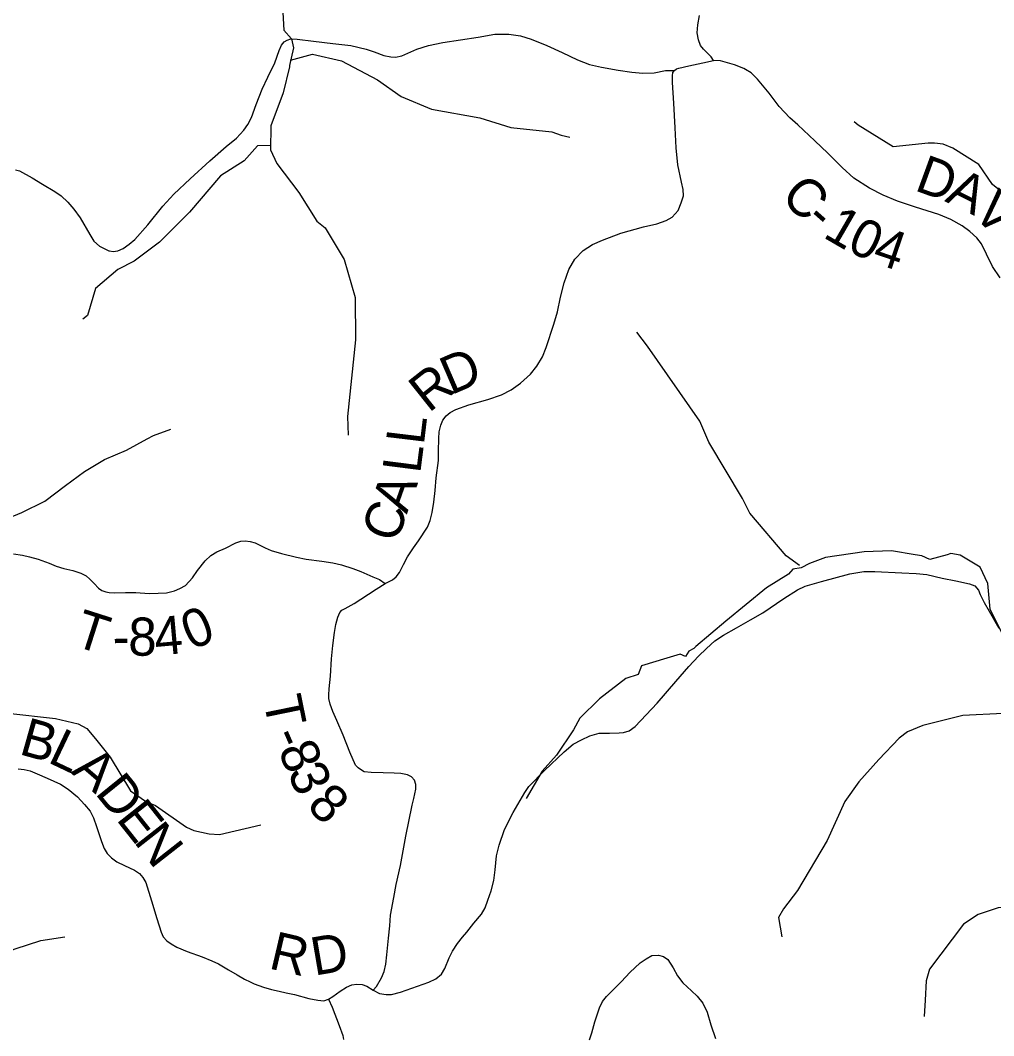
# Model space of a CAD drawing. Extents: x -1.8 to 75.7, y -2 to 25.
# Drawn here: x 6.256 to 7.704, y 15.471 to 16.983 of the extents above; entities that cross this region are included whole.
import ezdxf

# ---------------------------------------------------------------- set-up
doc = ezdxf.new("R2010")
doc.units = 0
for name, color, linetype in [('GM_X_County_Road', 7, 'Continuous'), ('GM_X_County_Road_Text', 7, 'Continuous'), ('GM_X_Minor_River', 7, 'Continuous'), ('GM_X_Township_Road', 7, 'Continuous'), ('GM_X_Township_Road_Text', 7, 'Continuous')]:
    doc.layers.add(name, color=color, linetype=linetype)

msp = doc.modelspace()

# ---------------------------------------------------------------- linework, layer by layer
at = {"layer": 'GM_X_County_Road'}
for points in [[(7.3351, 16.9097), (7.3325, 16.9113), (7.3187, 16.9167), (7.2978, 16.9227), (7.2872, 16.9231), (7.2841, 16.9283), (7.2785, 16.9339), (7.2724, 16.9398), (7.2679, 16.9452), (7.2648, 16.954), (7.2632, 16.9642), (7.2638, 16.9759), (7.2667, 16.9899)], [(7.7142, 16.5994), (7.7026, 16.6165), (7.6935, 16.6347), (7.6864, 16.6502), (7.6793, 16.659), (7.669, 16.6686), (7.6577, 16.6769), (7.6405, 16.6865), (7.6228, 16.6936), (7.5878, 16.7047), (7.5615, 16.7137), (7.5401, 16.7226), (7.5195, 16.7331), (7.4964, 16.7479), (7.479, 16.7638), (7.4574, 16.7849), (7.4383, 16.8036), (7.413, 16.8271), (7.401, 16.8377), (7.385, 16.8544), (7.3703, 16.8743), (7.3531, 16.8954), (7.3435, 16.9044), (7.3351, 16.9097)], [(6.2525, 15.8683), (6.2615, 15.8676), (6.2703, 15.8654), (6.2807, 15.8611), (6.2956, 15.8546), (6.3152, 15.8457), (6.3268, 15.8385), (6.3405, 15.8267), (6.3512, 15.8155), (6.3593, 15.8053), (6.3645, 15.7958), (6.369, 15.7829), (6.3763, 15.7606), (6.3805, 15.7499), (6.3848, 15.7423), (6.3912, 15.7359), (6.399, 15.7303), (6.4108, 15.7246), (6.4257, 15.7176), (6.433, 15.7129), (6.4381, 15.7068), (6.4422, 15.6991), (6.4506, 15.6722), (6.4587, 15.6456), (6.465, 15.6252), (6.4682, 15.6183), (6.4736, 15.6126), (6.4799, 15.6078), (6.4883, 15.6031), (6.5041, 15.5965), (6.5262, 15.5886), (6.5405, 15.5828), (6.5507, 15.5782), (6.5653, 15.5695), (6.5784, 15.5618), (6.5891, 15.5554), (6.5976, 15.5516), (6.6037, 15.5484), (6.6175, 15.5435), (6.6293, 15.5401), (6.641, 15.5376), (6.6514, 15.5351), (6.6638, 15.5328), (6.685, 15.5268), (6.6982, 15.524), (6.7074, 15.5234), (6.7142, 15.5256), (6.7207, 15.5297), (6.7318, 15.5376), (6.7413, 15.5433), (6.7492, 15.5469), (6.7567, 15.5482), (6.7644, 15.5473), (6.7714, 15.5448), (6.781, 15.5389), (6.7903, 15.534), (6.8002, 15.5324), (6.8082, 15.5326), (6.8217, 15.5363), (6.8466, 15.5451), (6.8635, 15.5509), (6.874, 15.5561), (6.8824, 15.563), (6.8875, 15.5712), (6.8939, 15.5871), (6.899, 15.5972), (6.9065, 15.6085), (6.9138, 15.6182), (6.9202, 15.6253), (6.9308, 15.6387), (6.9418, 15.6522), (6.9473, 15.6617), (6.9515, 15.6732), (6.9562, 15.6869), (6.9603, 15.7025), (6.9626, 15.7184), (6.9645, 15.7388), (6.9681, 15.7549), (6.9762, 15.7781), (6.9891, 15.8035), (7.0063, 15.8331), (7.0125, 15.8423), (7.0359, 15.866), (7.0652, 15.894), (7.0787, 15.9051), (7.0909, 15.9119), (7.1032, 15.9176), (7.1171, 15.9214), (7.1324, 15.9216), (7.147, 15.9221), (7.1534, 15.9225), (7.162, 15.9249), (7.1708, 15.9318), (7.2035, 15.9662), (7.2313, 15.9985), (7.2507, 16.0208), (7.2649, 16.0364), (7.277, 16.0479), (7.2894, 16.059), (7.3022, 16.0676), (7.3216, 16.0786), (7.3426, 16.0903), (7.3607, 16.1009), (7.3923, 16.1219), (7.4124, 16.1352), (7.4239, 16.1407), (7.4479, 16.1475), (7.4901, 16.1586), (7.5111, 16.1623), (7.5276, 16.1622), (7.5679, 16.1603), (7.589, 16.1595), (7.6047, 16.1576), (7.6275, 16.1524), (7.6479, 16.1483), (7.6683, 16.1441), (7.6766, 16.1409), (7.6818, 16.1343), (7.6844, 16.128), (7.6903, 16.1161), (7.6977, 16.1031), (7.7119, 16.0781)], [(7.1028, 15.4649), (7.1062, 15.4757), (7.1108, 15.4917), (7.1175, 15.513), (7.1223, 15.5223), (7.1281, 15.5297), (7.1502, 15.5518), (7.1628, 15.5656), (7.1782, 15.5795), (7.1871, 15.5858), (7.1957, 15.5906), (7.2053, 15.5914), (7.2128, 15.5893), (7.2196, 15.5849), (7.2274, 15.5721), (7.2336, 15.5604), (7.2419, 15.55), (7.2547, 15.5381), (7.2633, 15.5301), (7.2713, 15.5199), (7.2778, 15.5065), (7.2833, 15.4874), (7.2904, 15.4673)], [(6.7142, 15.5256), (6.7199, 15.5137), (6.7302, 15.4866), (6.7357, 15.4718), (6.7368, 15.4657)]]:
    msp.add_lwpolyline(points, dxfattribs=at)
at = {"layer": 'GM_X_Minor_River'}
for points in [[(6.5731, 17.2447), (6.5733, 17.2424), (6.5763, 17.2257), (6.5994, 17.1892), (6.618, 17.1471), (6.6437, 17.0992), (6.6521, 17.0749), (6.6536, 17.0449), (6.6521, 17.0198), (6.6465, 16.9943), (6.6476, 16.9681), (6.6594, 16.9552), (6.662, 16.9419), (6.656, 16.9157), (6.6564, 16.9134), (6.6466, 16.875), (6.6285, 16.8256), (6.6278, 16.7898), (6.6376, 16.7697), (6.6702, 16.7264), (6.6967, 16.6836), (6.7091, 16.6741), (6.7375, 16.6269)], [(6.6576, 16.9233), (6.6904, 16.9324), (6.7335, 16.9227), (6.7871, 16.8944), (6.8226, 16.8693), (6.8678, 16.8504), (6.9396, 16.8375), (6.9857, 16.8235), (7.0467, 16.8166), (7.0605, 16.8116), (7.0737, 16.8089)], [(7.7105, 16.7318), (7.7028, 16.7385), (7.6821, 16.7684), (7.6436, 16.7924), (7.629, 16.7986), (7.6162, 16.8001), (7.6071, 16.7997), (7.5548, 16.7945), (7.5028, 16.8265), (7.4966, 16.8317)], [(6.6279, 16.7964), (6.6085, 16.796), (6.5889, 16.7735), (6.5537, 16.7513), (6.5074, 16.6972), (6.4629, 16.6525), (6.4251, 16.6242), (6.4009, 16.612), (6.3676, 16.5837), (6.3557, 16.5434), (6.3486, 16.5377)], [(6.7375, 16.6269), (6.7542, 16.5701), (6.7545, 16.507), (6.7424, 16.3931), (6.7438, 16.3654)], [(7.4153, 16.1713), (7.3953, 16.1856), (7.3413, 16.2492), (7.3303, 16.2712), (7.2803, 16.3548), (7.2669, 16.386), (7.189, 16.4975), (7.173, 16.5185)], [(6.2049, 16.2283), (6.2578, 16.25), (6.2918, 16.2668), (6.3228, 16.2901), (6.3511, 16.3114), (6.381, 16.329), (6.4138, 16.3428), (6.4444, 16.3599), (6.4539, 16.3649), (6.4796, 16.3744)], [(7.7232, 16.0584), (7.7043, 16.096), (7.6993, 16.1063), (7.6955, 16.1443), (7.6845, 16.1689), (7.6543, 16.1867), (7.6407, 16.189), (7.6354, 16.1871), (7.6093, 16.1802), (7.5976, 16.1858), (7.5874, 16.187), (7.5522, 16.193), (7.5118, 16.1917), (7.4543, 16.1829), (7.4305, 16.1741), (7.418, 16.1676), (7.4056, 16.166), (7.3991, 16.1584), (7.3663, 16.1378), (7.3055, 16.0883), (7.2613, 16.0509), (7.2579, 16.0479), (7.2507, 16.0437), (7.2458, 16.036), (7.2375, 16.0391), (7.2178, 16.0333), (7.1804, 16.0218), (7.1751, 16.0089), (7.157, 16.0028), (7.1177, 15.9727), (7.0886, 15.9441), (7.0788, 15.9266), (7.0539, 15.8889), (7.0323, 15.8653), (7.0086, 15.8246)], [(6.0038, 16.0741), (6.0123, 16.0492), (6.0352, 16.0227), (6.0596, 16.0077), (6.1006, 15.9999), (6.1786, 15.9783), (6.2372, 15.9516), (6.3078, 15.9436), (6.3416, 15.9354), (6.3546, 15.9287), (6.3676, 15.9132), (6.3894, 15.8859), (6.4197, 15.836), (6.4433, 15.8194), (6.457, 15.8141), (6.5031, 15.7817), (6.5138, 15.7765), (6.5369, 15.772), (6.5521, 15.7706), (6.6135, 15.7853)], [(7.7295, 15.9561), (7.7186, 15.9508), (7.6583, 15.9478), (7.5988, 15.933), (7.5763, 15.9236), (7.5638, 15.9142), (7.5337, 15.8824), (7.5035, 15.8492), (7.4829, 15.8197), (7.4564, 15.7617), (7.4124, 15.6875), (7.3918, 15.6602), (7.3842, 15.6474), (7.3889, 15.6184)], [(7.8443, 15.9137), (7.8208, 15.8303), (7.8113, 15.7785), (7.8075, 15.7422), (7.7831, 15.7103), (7.765, 15.6748), (7.7531, 15.6665), (7.7109, 15.6614), (7.6812, 15.6517), (7.6596, 15.6372), (7.6088, 15.5705), (7.6037, 15.5528), (7.6024, 15.524), (7.601, 15.5001)], [(5.9012, 15.3623), (5.9344, 15.3711), (5.9613, 15.3913), (5.9703, 15.4031), (5.9813, 15.4093), (6.0147, 15.4577), (6.054, 15.4954), (6.0914, 15.529), (6.1488, 15.5624), (6.248, 15.6008), (6.2863, 15.6128), (6.3219, 15.6183)]]:
    msp.add_lwpolyline(points, dxfattribs=at)
at = {"layer": 'GM_X_Township_Road'}
for points in [[(6.3882, 16.6395), (6.3937, 16.6387), (6.4005, 16.6396), (6.4085, 16.643), (6.4177, 16.6496), (6.426, 16.6563), (6.4455, 16.6783), (6.4679, 16.7063), (6.484, 16.7239), (6.5084, 16.747), (6.5378, 16.7737), (6.5621, 16.7951), (6.5773, 16.8076), (6.5884, 16.8191), (6.5944, 16.8277), (6.5995, 16.8382), (6.6066, 16.8574), (6.6156, 16.8801), (6.6242, 16.8983), (6.6342, 16.9197), (6.6408, 16.9381), (6.6443, 16.946), (6.6483, 16.9509), (6.6526, 16.9535), (6.6582, 16.9554), (6.6674, 16.955), (6.6922, 16.952), (6.7209, 16.9484), (6.7474, 16.9451), (6.7703, 16.94), (6.7825, 16.9359), (6.7968, 16.9306), (6.8073, 16.9285), (6.8142, 16.9278), (6.8236, 16.93), (6.8458, 16.9399), (6.8632, 16.9451), (6.8846, 16.9499), (6.937, 16.9578), (6.962, 16.9621), (6.9826, 16.9621), (6.9999, 16.9597), (7.0162, 16.9546), (7.0391, 16.9454), (7.0622, 16.9351), (7.0851, 16.9242), (7.1026, 16.9171), (7.1208, 16.913), (7.1454, 16.9086), (7.1658, 16.9057), (7.182, 16.9042), (7.199, 16.9047), (7.2157, 16.9079), (7.2291, 16.9083)], [(6.781, 15.5389), (6.7858, 15.5444), (6.7933, 15.5575), (6.7973, 15.567), (6.7996, 15.578), (6.801, 15.5918), (6.8036, 15.6165), (6.8054, 15.6348), (6.8068, 15.6506), (6.8113, 15.677), (6.8152, 15.6966), (6.8213, 15.7244), (6.8292, 15.7682), (6.8389, 15.8143), (6.8412, 15.8245), (6.8443, 15.8383), (6.8445, 15.845), (6.8423, 15.8516), (6.8378, 15.8568), (6.8321, 15.8597), (6.8222, 15.8616), (6.8122, 15.8622), (6.7957, 15.8625), (6.7779, 15.8629), (6.7675, 15.8643), (6.7618, 15.8674), (6.7582, 15.8701), (6.7546, 15.8738), (6.746, 15.8932), (6.7359, 15.9185), (6.7269, 15.9406), (6.7208, 15.9539), (6.7167, 15.965), (6.7149, 15.9734), (6.7147, 15.9786), (6.7155, 15.9878), (6.7171, 16.0064), (6.7187, 16.0323), (6.7205, 16.052), (6.723, 16.0714), (6.725, 16.0836), (6.728, 16.0944), (6.7314, 16.1013), (6.7343, 16.1046), (6.7391, 16.1073), (6.7527, 16.1149), (6.7625, 16.1211), (6.7853, 16.136), (6.7987, 16.1442), (6.8097, 16.15), (6.815, 16.1546), (6.8201, 16.1609), (6.8258, 16.1726), (6.8319, 16.1839), (6.8409, 16.1974), (6.8482, 16.2081), (6.8615, 16.2283), (6.8655, 16.2384), (6.8685, 16.2499), (6.8711, 16.2655), (6.8732, 16.2831), (6.8747, 16.3017), (6.8779, 16.3276), (6.8782, 16.3413), (6.8786, 16.3603), (6.8792, 16.37), (6.8814, 16.38), (6.8846, 16.3875), (6.8895, 16.3941), (6.8955, 16.3991), (6.9036, 16.4036), (6.9233, 16.4104), (6.9513, 16.4185), (6.9717, 16.4254), (6.986, 16.4327), (7.0001, 16.4425), (7.0149, 16.456), (7.0245, 16.4678), (7.0329, 16.4819), (7.0384, 16.496), (7.0498, 16.5304), (7.0553, 16.5489), (7.0598, 16.5707), (7.065, 16.5921), (7.0718, 16.6118), (7.0808, 16.6274), (7.0934, 16.6402), (7.1071, 16.649), (7.1223, 16.6554), (7.1493, 16.6659), (7.1833, 16.6755), (7.203, 16.68), (7.2169, 16.6849), (7.2259, 16.6899), (7.2347, 16.6995), (7.2394, 16.7113), (7.2428, 16.7215), (7.242, 16.7308), (7.2396, 16.7421), (7.2342, 16.7678), (7.2319, 16.793), (7.2302, 16.823), (7.2282, 16.8595), (7.2262, 16.89), (7.2265, 16.9003), (7.2269, 16.9049), (7.2291, 16.9083), (7.2321, 16.9105), (7.236, 16.9116), (7.2508, 16.9152), (7.2716, 16.9194), (7.2872, 16.9231)], [(6.2485, 16.7604), (6.2544, 16.7588), (6.273, 16.7483), (6.2888, 16.7389), (6.3068, 16.7282), (6.3164, 16.7213), (6.3261, 16.7123), (6.3351, 16.7016), (6.3445, 16.6886), (6.3588, 16.664), (6.3652, 16.6539), (6.3732, 16.6464), (6.3813, 16.6424), (6.3875, 16.6396), (6.3882, 16.6395)], [(6.2454, 16.1886), (6.2588, 16.1866), (6.2692, 16.1839), (6.282, 16.1805), (6.2983, 16.1746), (6.3091, 16.1704), (6.3202, 16.167), (6.3336, 16.164), (6.3458, 16.1599), (6.3534, 16.1559), (6.3591, 16.1511), (6.3654, 16.1446), (6.372, 16.1376), (6.3771, 16.1342), (6.3826, 16.132), (6.3878, 16.1311), (6.3957, 16.1306), (6.4122, 16.1308), (6.4277, 16.131), (6.4474, 16.1297), (6.4609, 16.1299), (6.4729, 16.1306), (6.4853, 16.1337), (6.493, 16.1369), (6.5014, 16.1417), (6.5116, 16.1529), (6.5195, 16.1638), (6.5308, 16.1782), (6.5393, 16.1859), (6.5479, 16.1916), (6.5608, 16.1972), (6.5762, 16.2049), (6.5839, 16.2076), (6.59, 16.2081), (6.5978, 16.207), (6.6049, 16.2049), (6.6198, 16.1975), (6.629, 16.1936), (6.6444, 16.1891), (6.6668, 16.1834), (6.6812, 16.1807), (6.7043, 16.1776), (6.7205, 16.1753), (6.7338, 16.1721), (6.7506, 16.1667), (6.7625, 16.1624), (6.7802, 16.1546), (6.7901, 16.1503), (6.7987, 16.1442)]]:
    msp.add_lwpolyline(points, dxfattribs=at)

# ---------------------------------------------------------------- texts
at = {"layer": 'GM_X_County_Road_Text'}
for s, rotation, p in [('D', 340.0016, (7.585, 16.7303)), ('A', 333.7917, (7.6305, 16.7139)), ('C', 315.2926, (7.3855, 16.7185)), ('V', 314.687, (7.6713, 16.6947)), ('-', 318.6757, (7.4213, 16.6831)), ('1', 329.9072, (7.4487, 16.6607)), ('0', 334.9905, (7.4839, 16.6406)), ('4', 341.0668, (7.5217, 16.6233)), ('B', 344.2757, (6.252, 15.8909)), ('L', 334.585, (6.2946, 15.8791)), ('A', 319.2812, (6.3296, 15.8631)), ('D', 308.9574, (6.3656, 15.8324)), ('E', 308.4476, (6.397, 15.7936)), ('N', 308.071, (6.4233, 15.7604)), ('R', 346.8887, (6.6237, 15.5718)), ('D', 9.6833, (6.6932, 15.5605))]:
    msp.add_text(s, height=0.0568, rotation=rotation, dxfattribs=at).set_placement(p)
at = {"layer": 'GM_X_Township_Road_Text'}
for s, rotation, p in [('D', 23.3981, (6.8966, 16.4245)), ('R', 38.4867, (6.8634, 16.3975)), ('L', 83.1536, (6.8561, 16.3496)), ('L', 82.7316, (6.8507, 16.307)), ('A', 70.3854, (6.8308, 16.2469)), ('C', 70.9646, (6.8157, 16.2029)), ('T', 342.2776, (6.3326, 16.0526)), ('0', 22.7305, (6.5101, 16.0447)), ('8', 359.0556, (6.4159, 16.0373)), ('4', 5.1397, (6.4572, 16.037)), ('-', 1.3506, (6.3934, 16.0368)), ('T', 281.5419, (6.6169, 15.972)), ('-', 293.6691, (6.6294, 15.9179)), ('8', 292.476, (6.6386, 15.8968)), ('3', 293.5432, (6.6525, 15.8634)), ('8', 315.7083, (6.68, 15.8117))]:
    msp.add_text(s, height=0.0568, rotation=rotation, dxfattribs=at).set_placement(p)

doc.saveas('drawing.dxf')
